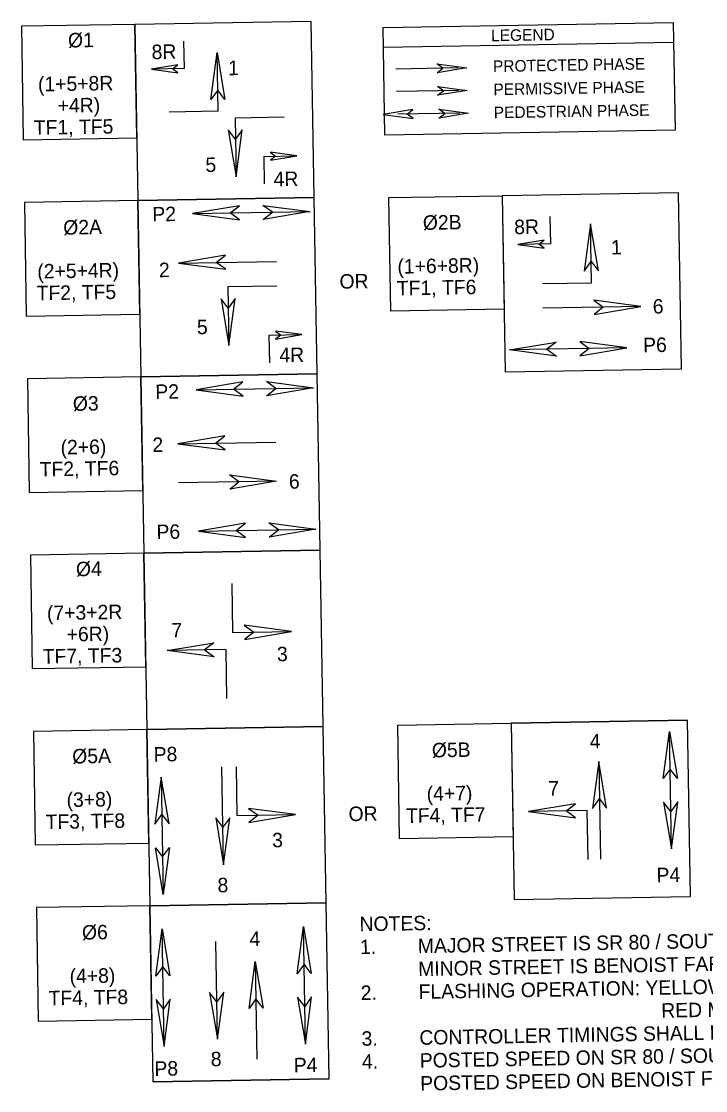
# Model space of a CAD drawing. Extents: x 924596 to 926137, y 853397 to 853834.
# Drawn here: x 925337 to 925469.4, y 853400.9 to 853607.8 of the extents above; entities that cross this region are included whole.
import ezdxf

# ---------------------------------------------------------------- set-up
doc = ezdxf.new("R2010")
doc.units = 0
doc.layers.add('SignalSOP', color=7, linetype='Continuous')
doc.layers.add('TextMisc', color=7, linetype='Continuous')

msp = doc.modelspace()

# ---------------------------------------------------------------- linework, layer by layer
at = {"layer": 'SignalSOP'}
for p, q in [((925359, 853607.18), (925337.03, 853606.8)), ((925393.11, 853607.76), (925359, 853607.18)), ((925359, 853607.18), (925359.58, 853573.07)), ((925359.38, 853585.2), (925359, 853607.18)), ((925393.69, 853573.65), (925393.11, 853607.76)), ((925337.03, 853606.8), (925337.4, 853584.83)), ((925368.57, 853598.62), (925368.48, 853603.95)), ((925407.09, 853602.79), (925463.24, 853603.74)), ((925373.69, 853592.62), (925374.89, 853601.73)), ((925375.09, 853590.36), (925374.89, 853601.73)), ((925374.89, 853601.73), (925376.41, 853592.66)), ((925367.28, 853599.37), (925362.18, 853598.51)), ((925366.27, 853598.58), (925367.28, 853599.37)), ((925421.52, 853598.75), (925409.52, 853598.54)), ((925418.61, 853598.7), (925417.45, 853599.54)), ((925417.45, 853599.54), (925423.22, 853598.78)), ((925423.22, 853598.78), (925417.48, 853597.82)), ((925368.57, 853598.62), (925362.18, 853598.51)), ((925362.18, 853598.51), (925367.3, 853597.83)), ((925367.3, 853597.83), (925366.27, 853598.58)), ((925417.48, 853597.82), (925418.61, 853598.7)), ((925418.69, 853594.34), (925417.52, 853595.18)), ((925417.52, 853595.18), (925423.3, 853594.41)), ((925375.02, 853594.46), (925373.69, 853592.62)), ((925376.41, 853592.66), (925375.02, 853594.46)), ((925421.59, 853594.39), (925409.59, 853594.18)), ((925423.3, 853594.41), (925417.55, 853593.45)), ((925417.55, 853593.45), (925418.69, 853594.34)), ((925412.8, 853590.71), (925407.05, 853589.74)), ((925411.66, 853589.82), (925412.8, 853590.71)), ((925418.95, 853589.95), (925417.78, 853590.79)), ((925417.78, 853590.79), (925423.56, 853590.02)), ((925375.09, 853590.36), (925365.61, 853590.2)), ((925387.85, 853589.2), (925378.37, 853589.04)), ((925378.37, 853589.04), (925378.57, 853577.67)), ((925407.05, 853589.74), (925412.83, 853588.98)), ((925421.85, 853590), (925409.85, 853589.79)), ((925412.83, 853588.98), (925411.66, 853589.82)), ((925423.56, 853590.02), (925417.81, 853589.06)), ((925417.81, 853589.06), (925418.95, 853589.95)), ((925378.44, 853584.95), (925377.05, 853586.74)), ((925377.05, 853586.74), (925378.57, 853577.67)), ((925379.78, 853586.79), (925378.44, 853584.95)), ((925378.57, 853577.67), (925379.78, 853586.79)), ((925337.4, 853584.83), (925359.38, 853585.2)), ((925390.31, 853581.75), (925385.18, 853582.43)), ((925385.18, 853582.43), (925386.22, 853581.68)), ((925383.92, 853581.64), (925390.31, 853581.75)), ((925383.92, 853581.64), (925384.01, 853576.31)), ((925385.21, 853580.89), (925390.31, 853581.75)), ((925386.22, 853581.68), (925385.21, 853580.89)), ((925408.12, 853573.65), (925430.09, 853574.02)), ((925464.2, 853574.6), (925430.09, 853574.02)), ((925430.09, 853574.02), (925430.67, 853539.92)), ((925430.09, 853574.02), (925430.46, 853552.05)), ((925464.78, 853540.5), (925464.2, 853574.6)), ((925359.58, 853573.07), (925337.61, 853572.7)), ((925337.61, 853572.7), (925337.98, 853550.72)), ((925359.58, 853573.07), (925393.69, 853573.65)), ((925393.69, 853573.65), (925359.58, 853573.07)), ((925359.58, 853573.07), (925360.16, 853538.96)), ((925359.96, 853551.09), (925359.58, 853573.07)), ((925379.21, 853572.08), (925370.14, 853570.56)), ((925377.41, 853570.69), (925379.21, 853572.08)), ((925385.6, 853570.83), (925383.76, 853572.16)), ((925383.76, 853572.16), (925392.88, 853570.95)), ((925394.27, 853539.54), (925393.69, 853573.65)), ((925408.49, 853551.68), (925408.12, 853573.65)), ((925370.14, 853570.56), (925392.88, 853570.95)), ((925370.14, 853570.56), (925379.26, 853569.35)), ((925379.26, 853569.35), (925377.41, 853570.69)), ((925392.88, 853570.95), (925383.8, 853569.43)), ((925383.8, 853569.43), (925385.6, 853570.83)), ((925439.47, 853564.69), (925439.38, 853570.01)), ((925447.16, 853568.56), (925445.95, 853559.44)), ((925447.36, 853557.19), (925447.16, 853568.56)), ((925448.68, 853559.48), (925447.16, 853568.56)), ((925438.17, 853565.43), (925433.07, 853564.58)), ((925439.47, 853564.69), (925433.07, 853564.58)), ((925433.07, 853564.58), (925438.2, 853563.9)), ((925437.16, 853564.65), (925438.17, 853565.43)), ((925438.2, 853563.9), (925437.16, 853564.65)), ((925376.52, 853562.51), (925367.45, 853560.99)), ((925374.72, 853561.11), (925376.52, 853562.51)), ((925367.45, 853560.99), (925386.4, 853561.31)), ((925367.45, 853560.99), (925376.57, 853559.78)), ((925376.57, 853559.78), (925374.72, 853561.11)), ((925445.95, 853559.44), (925447.29, 853561.28)), ((925447.29, 853561.28), (925448.68, 853559.48)), ((925386.48, 853556.54), (925377, 853556.38)), ((925377, 853556.38), (925377.2, 853545.01)), ((925437.88, 853557.03), (925447.36, 853557.19)), ((925377.07, 853552.29), (925375.68, 853554.08)), ((925375.68, 853554.08), (925377.2, 853545.01)), ((925378.41, 853554.13), (925377.07, 853552.29)), ((925377.2, 853545.01), (925378.41, 853554.13)), ((925456.91, 853552.58), (925447.79, 853553.78)), ((925447.79, 853553.78), (925449.63, 853552.45)), ((925430.46, 853552.05), (925408.49, 853551.68)), ((925456.91, 853552.58), (925437.96, 853552.25)), ((925447.84, 853551.06), (925456.91, 853552.58)), ((925449.63, 853552.45), (925447.84, 853551.06)), ((925337.98, 853550.72), (925359.96, 853551.09)), ((925384.92, 853547.03), (925391.32, 853547.14)), ((925384.92, 853547.03), (925385.02, 853541.7)), ((925391.32, 853547.14), (925386.19, 853547.82)), ((925386.19, 853547.82), (925387.23, 853547.07)), ((925386.22, 853546.29), (925391.32, 853547.14)), ((925387.23, 853547.07), (925386.22, 853546.29)), ((925431.46, 853544.19), (925440.53, 853545.71)), ((925440.53, 853545.71), (925438.73, 853544.32)), ((925454.19, 853544.58), (925445.07, 853545.79)), ((925445.07, 853545.79), (925446.92, 853544.45)), ((925454.19, 853544.58), (925431.46, 853544.19)), ((925440.57, 853542.98), (925431.46, 853544.19)), ((925438.73, 853544.32), (925440.57, 853542.98)), ((925445.12, 853543.06), (925454.19, 853544.58)), ((925446.92, 853544.45), (925445.12, 853543.06)), ((925360.16, 853538.96), (925338.19, 853538.59)), ((925360.16, 853538.96), (925394.27, 853539.54)), ((925394.27, 853539.54), (925360.16, 853538.96)), ((925360.16, 853538.96), (925360.74, 853504.86)), ((925360.54, 853516.99), (925360.16, 853538.96)), ((925394.85, 853505.44), (925394.27, 853539.54)), ((925430.67, 853539.92), (925464.78, 853540.5)), ((925338.19, 853538.59), (925338.56, 853516.61)), ((925379.9, 853537.98), (925370.83, 853536.46)), ((925370.83, 853536.46), (925393.57, 853536.84)), ((925378.1, 853536.58), (925379.9, 853537.98)), ((925386.29, 853536.72), (925384.45, 853538.05)), ((925384.45, 853538.05), (925393.57, 853536.84)), ((925393.57, 853536.84), (925384.49, 853535.33)), ((925384.49, 853535.33), (925386.29, 853536.72)), ((925370.83, 853536.46), (925379.95, 853535.25)), ((925379.95, 853535.25), (925378.1, 853536.58)), ((925376.41, 853527.56), (925367.33, 853526.04)), ((925367.33, 853526.04), (925386.28, 853526.36)), ((925374.61, 853526.16), (925376.41, 853527.56)), ((925367.33, 853526.04), (925376.45, 853524.83)), ((925376.45, 853524.83), (925374.61, 853526.16)), ((925386.41, 853518.78), (925367.46, 853518.46)), ((925379.13, 853518.66), (925377.29, 853519.99)), ((925377.29, 853519.99), (925386.41, 853518.78)), ((925386.41, 853518.78), (925377.34, 853517.26)), ((925377.34, 853517.26), (925379.13, 853518.66)), ((925338.56, 853516.61), (925360.54, 853516.99)), ((925380.37, 853510.63), (925371.29, 853509.11)), ((925378.57, 853509.23), (925380.37, 853510.63)), ((925386.76, 853509.37), (925384.91, 853510.7)), ((925384.91, 853510.7), (925394.03, 853509.5)), ((925371.29, 853509.11), (925394.03, 853509.5)), ((925371.29, 853509.11), (925380.41, 853507.9)), ((925380.41, 853507.9), (925378.57, 853509.23)), ((925394.03, 853509.5), (925384.96, 853507.98)), ((925384.96, 853507.98), (925386.76, 853509.37)), ((925360.74, 853504.86), (925338.77, 853504.48)), ((925338.77, 853504.48), (925339.14, 853482.51)), ((925360.74, 853504.86), (925394.85, 853505.44)), ((925394.85, 853505.44), (925360.74, 853504.86)), ((925394.85, 853505.44), (925360.74, 853504.86)), ((925360.74, 853504.86), (925361.32, 853470.75)), ((925361.12, 853482.88), (925360.74, 853504.86)), ((925395.43, 853471.33), (925394.85, 853505.44)), ((925377.75, 853498.97), (925377.91, 853489.49)), ((925377.91, 853489.49), (925389.28, 853489.69)), ((925389.28, 853489.69), (925380.16, 853490.9)), ((925380.16, 853490.9), (925382, 853489.56)), ((925380.21, 853488.17), (925389.28, 853489.69)), ((925382, 853489.56), (925380.21, 853488.17)), ((925365.22, 853486.02), (925374.29, 853487.53)), ((925374.29, 853487.53), (925372.49, 853486.14)), ((925376.59, 853486.21), (925365.22, 853486.02)), ((925374.34, 853484.81), (925365.22, 853486.02)), ((925372.49, 853486.14), (925374.34, 853484.81)), ((925376.59, 853486.21), (925376.75, 853476.74)), ((925339.14, 853482.51), (925361.12, 853482.88)), ((925465.93, 853472.53), (925431.83, 853471.95)), ((925431.83, 853471.95), (925465.93, 853472.53)), ((925466.51, 853438.42), (925465.93, 853472.53)), ((925361.32, 853470.75), (925339.35, 853470.37)), ((925361.32, 853470.75), (925395.43, 853471.33)), ((925395.43, 853471.33), (925361.32, 853470.75)), ((925361.32, 853470.75), (925395.43, 853471.33)), ((925395.43, 853471.33), (925361.32, 853470.75)), ((925361.32, 853470.75), (925361.9, 853436.64)), ((925361.7, 853448.77), (925361.32, 853470.75)), ((925396.01, 853437.22), (925395.43, 853471.33)), ((925409.85, 853471.57), (925431.83, 853471.95)), ((925410.23, 853449.6), (925409.85, 853471.57)), ((925431.83, 853471.95), (925432.41, 853437.84)), ((925431.83, 853471.95), (925432.2, 853449.97)), ((925339.35, 853470.37), (925339.72, 853448.4)), ((925461.24, 853461.24), (925462.45, 853470.36)), ((925462.83, 853447.62), (925462.45, 853470.36)), ((925462.45, 853470.36), (925463.97, 853461.28)), ((925448.76, 853464.57), (925447.55, 853455.46)), ((925448.76, 853464.57), (925449.08, 853445.63)), ((925450.28, 853455.5), (925448.76, 853464.57)), ((925376.16, 853444.55), (925375.84, 853463.49)), ((925378.57, 853463.54), (925378.73, 853454.07)), ((925462.57, 853463.08), (925461.24, 853461.24)), ((925463.97, 853461.28), (925462.57, 853463.08)), ((925364.08, 853461.53), (925362.87, 853452.42)), ((925364.08, 853461.53), (925364.46, 853438.8)), ((925365.6, 853452.46), (925364.08, 853461.53)), ((925444.24, 853456.38), (925435.17, 853454.87)), ((925442.44, 853454.99), (925444.24, 853456.38)), ((925447.55, 853455.46), (925448.88, 853457.3)), ((925448.88, 853457.3), (925450.28, 853455.5)), ((925462.71, 853454.89), (925461.31, 853456.69)), ((925461.31, 853456.69), (925462.83, 853447.62)), ((925464.04, 853456.74), (925462.71, 853454.89)), ((925462.83, 853447.62), (925464.04, 853456.74)), ((925362.87, 853452.42), (925364.2, 853454.26)), ((925364.2, 853454.26), (925365.6, 853452.46)), ((925378.73, 853454.07), (925390.1, 853454.26)), ((925390.1, 853454.26), (925380.98, 853455.47)), ((925380.98, 853455.47), (925382.83, 853454.14)), ((925381.03, 853452.74), (925390.1, 853454.26)), ((925382.83, 853454.14), (925381.03, 853452.74)), ((925446.54, 853455.06), (925435.17, 853454.87)), ((925435.17, 853454.87), (925444.28, 853453.66)), ((925444.28, 853453.66), (925442.44, 853454.99)), ((925446.7, 853445.59), (925446.54, 853455.06)), ((925376.04, 853451.82), (925374.64, 853453.62)), ((925374.64, 853453.62), (925376.16, 853444.55)), ((925377.37, 853453.66), (925376.04, 853451.82)), ((925376.16, 853444.55), (925377.37, 853453.66)), ((925432.2, 853449.97), (925410.23, 853449.6)), ((925339.72, 853448.4), (925361.7, 853448.77)), ((925364.46, 853438.8), (925362.95, 853447.87)), ((925362.95, 853447.87), (925364.34, 853446.07)), ((925364.34, 853446.07), (925365.67, 853447.92)), ((925365.67, 853447.92), (925364.46, 853438.8)), ((925432.41, 853437.84), (925466.51, 853438.42)), ((925361.9, 853436.64), (925339.93, 853436.27)), ((925339.93, 853436.27), (925340.3, 853414.29)), ((925361.9, 853436.64), (925396.01, 853437.22)), ((925361.9, 853436.64), (925396.01, 853437.22)), ((925396.01, 853437.22), (925361.9, 853436.64)), ((925361.9, 853436.64), (925362.48, 853402.53)), ((925362.28, 853414.67), (925361.9, 853436.64)), ((925396.59, 853403.11), (925396.01, 853437.22)), ((925363.04, 853423.03), (925364.25, 853432.15)), ((925364.25, 853432.15), (925365.77, 853423.08)), ((925364.64, 853409.41), (925364.25, 853432.15)), ((925390.39, 853423.49), (925391.6, 853432.61)), ((925391.98, 853409.87), (925391.6, 853432.61)), ((925391.6, 853432.61), (925393.12, 853423.54)), ((925374.97, 853410.79), (925374.65, 853429.74)), ((925381.09, 853416.75), (925382.3, 853425.87)), ((925382.3, 853425.87), (925382.62, 853406.92)), ((925382.3, 853425.87), (925383.82, 853416.8)), ((925391.72, 853425.34), (925390.39, 853423.49)), ((925393.12, 853423.54), (925391.72, 853425.34)), ((925364.37, 853424.87), (925363.04, 853423.03)), ((925365.77, 853423.08), (925364.37, 853424.87)), ((925374.85, 853418.07), (925373.45, 853419.86)), ((925373.45, 853419.86), (925374.97, 853410.79)), ((925376.18, 853419.91), (925374.85, 853418.07)), ((925374.97, 853410.79), (925376.18, 853419.91)), ((925391.86, 853417.15), (925390.47, 853418.95)), ((925390.47, 853418.95), (925391.98, 853409.87)), ((925393.19, 853418.99), (925391.86, 853417.15)), ((925391.98, 853409.87), (925393.19, 853418.99)), ((925364.51, 853416.69), (925363.12, 853418.48)), ((925363.12, 853418.48), (925364.64, 853409.41)), ((925365.84, 853418.53), (925364.51, 853416.69)), ((925364.64, 853409.41), (925365.84, 853418.53)), ((925382.42, 853418.59), (925381.09, 853416.75)), ((925383.82, 853416.8), (925382.42, 853418.59)), ((925340.3, 853414.29), (925362.28, 853414.67)), ((925362.48, 853402.53), (925396.59, 853403.11)), ((925396.59, 853403.11), (925362.48, 853402.53))]:
    msp.add_line(p, q, dxfattribs=at)
msp.add_lwpolyline([(925407.03, 853606.6), (925463.17, 853607.55), (925463.53, 853586.68), (925407.38, 853585.73)], close=True, dxfattribs=at)

# ---------------------------------------------------------------- texts
for s, height, p in [('Ø1', 2.8, (925346.07, 853602.7)), ('LEGEND', 2.24, (925427.94, 853603.9)), ('8R', 2.8, (925362.25, 853600.44)), ('1', 2.8, (925377.05, 853597.33)), ('PROTECTED PHASE', 2.24, (925428.31, 853597.95)), ('(1+5+8R', 2.8, (925340.26, 853594.2)), ('PERMISSIVE PHASE', 2.24, (925428.39, 853593.47)), ('+4R)', 2.8, (925344.07, 853590.07)), ('PEDESTRIAN PHASE', 2.24, (925428.46, 853588.99)), ('TF1, TF5', 2.8, (925339.45, 853585.79)), ('5', 2.8, (925372.67, 853578.6)), ('4R', 2.8, (925385.86, 853575.84)), ('P2', 2.8, (925362.39, 853569.04)), ('Ø2B', 2.8, (925414.74, 853567.41)), ('Ø2A', 2.8, (925345.15, 853566.47)), ('8R', 2.8, (925432.42, 853566.57)), ('1', 2.8, (925451.15, 853562.64)), ('(1+6+8R)', 2.8, (925409.82, 853558.93)), ('(2+5+4R)', 2.8, (925340.13, 853557.98)), ('2', 2.8, (925363.67, 853558.25)), ('OR', 2.8, (925398.61, 853556.03)), ('TF1, TF6', 2.8, (925409.7, 853554.72)), ('TF2, TF5', 2.8, (925339.99, 853553.78)), ('6', 2.8, (925459.23, 853551.2)), ('5', 2.8, (925371.02, 853547.21)), ('P6', 2.8, (925457.37, 853543.72)), ('4R', 2.8, (925386.97, 853541.78)), ('P2', 2.8, (925362.97, 853534.68)), ('Ø3', 2.8, (925347.01, 853532.39)), ('(2+6)', 2.8, (925344.64, 853523.94)), ('2', 2.8, (925362.41, 853524.42)), ('TF2, TF6', 2.8, (925340.59, 853519.68)), ('6', 2.8, (925388.82, 853517.32)), ('P6', 2.8, (925363.2, 853507.57)), ('Ø4', 2.8, (925347.61, 853500.38)), ('(7+3+2R', 2.8, (925342, 853491.88)), ('7', 2.8, (925366.09, 853488.54)), ('+6R)', 2.8, (925345.81, 853487.75)), ('TF7, TF3', 2.8, (925341.17, 853483.47)), ('3', 2.8, (925386.51, 853483.93)), ('4', 2.8, (925447.03, 853467.04)), ('Ø5A', 2.8, (925346.89, 853464.15)), ('P8', 2.8, (925362.65, 853464.52)), ('Ø5B', 2.8, (925416.48, 853465.33)), ('7', 2.8, (925439.01, 853457.94)), ('(3+8)', 2.8, (925345.8, 853455.73)), ('(4+7)', 2.8, (925415.48, 853456.92)), ('TF3, TF8', 2.8, (925341.73, 853451.46)), ('OR', 2.8, (925400.36, 853453)), ('TF4, TF7', 2.8, (925411.47, 853452.65)), ('3', 2.8, (925385.58, 853447.93)), ('P4', 2.8, (925459.96, 853441.17)), ('8', 2.8, (925375.01, 853439.22)), ('Ø6', 2.8, (925348.78, 853430.07)), ('4', 2.8, (925381.19, 853428.85)), ('(4+8)', 2.8, (925346.38, 853421.62)), ('TF4, TF8', 2.8, (925342.31, 853417.35)), ('8', 2.8, (925373.7, 853405.56)), ('P8', 2.8, (925362.8, 853403.71)), ('P4', 2.8, (925389.76, 853404.39))]:
    msp.add_text(s, height=height, rotation=0.9741, dxfattribs=at).set_placement(p)
at = {"layer": 'TextMisc'}
for s, p in [('NOTES:', (925402.49, 853431.69)), ('MAJOR STREET IS SR 80 / SOUTHERN BOULEVARD', (925413.77, 853427.45)), ('1.', (925402.57, 853427.26)), ('MINOR STREET IS BENOIST FARMS ROAD', (925413.84, 853423.02)), ('FLASHING OPERATION: YELLOW MOVEMENTS - 2,6', (925413.92, 853418.59)), ('2.', (925402.72, 853418.39)), ('  RED MOVEMENTS - ALL OTHERS', (925458.79, 853414.93)), ('CONTROLLER TIMINGS SHALL BE COORDINATED WITH PBCTED PRIOR TO FINAL ACCEPTANCE.', (925414.07, 853409.72)), ('3.', (925402.88, 853409.53)), ('POSTED SPEED ON SR 80 / SOUTHERN BOULEVARD = 50 MPH', (925414.15, 853405.29)), ('4.', (925402.95, 853405.09)), ('POSTED SPEED ON BENOIST FARMS RD. = 40 MPH', (925414.23, 853400.86))]:
    msp.add_text(s, height=2.8, rotation=0.9944, dxfattribs=at).set_placement(p)

doc.saveas('drawing.dxf')
